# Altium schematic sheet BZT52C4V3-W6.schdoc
size 127 x 101 mm
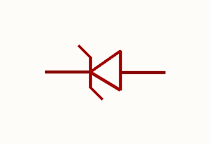
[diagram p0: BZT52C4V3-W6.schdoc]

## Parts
D?  bzt52c4v3_c364301  [SOD-123_L2.8-W1.8-LS3.7-RD]  (value not drawn)

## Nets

Not connected (* = marked no-connect by the designer): D? 1 2

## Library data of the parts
D? = bzt52c4v3_c364301: 二极管配置:1个独立式;稳压值(标称值):4.3V;稳压值(范围值):4.11V~4.52V;耗散功率(Pd):500mW;; Manufacturer: MDD(辰达半导体); Symbol: BZT52C4V3-W6; AddInBom: yes; ModelId: 7884390a25fb4c08947731ebfba7e3f8; ModelTransform: 144.8816,62.992,0,0,0,0,0,0,0; Diode Configuration: 1个独立式; Zener Voltage(Nom): 4.3V; Reverse Leakage Current (Ir): 5uA@1V; Pd - Power Dissipation: 500mW; Impedance(Zzt): 130Ω; Tolerance: ±5%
